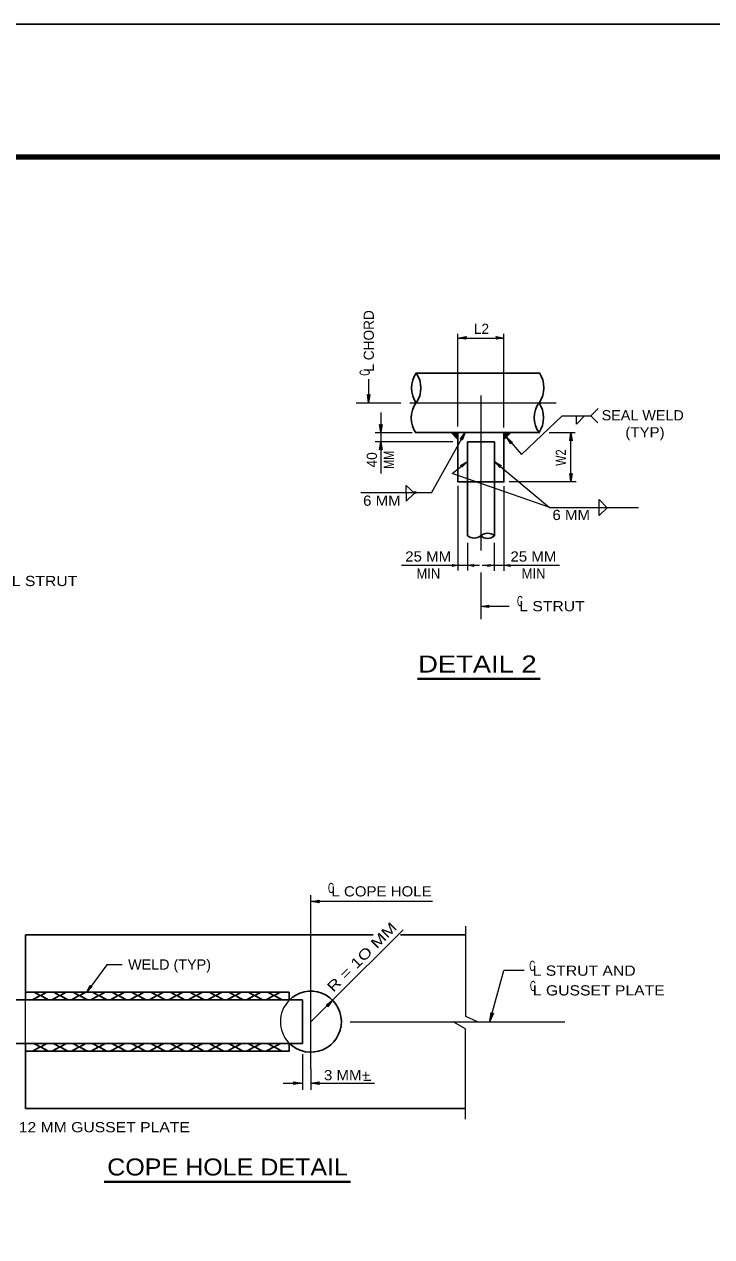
# Model space of a CAD drawing. Extents: x 312601.858 to 312602.699, y 144420.109 to 144420.704.
# Drawn here: x 312602.1064 to 312602.3083, y 144420.3472 to 144420.7035 of the extents above; entities that cross this region are included whole.
import ezdxf
from ezdxf.enums import TextEntityAlignment as Align

# ---------------------------------------------------------------- set-up
doc = ezdxf.new("R2010")
doc.units = 0
doc.header["$LTSCALE"] = 0.0012
doc.header["$PDMODE"] = 32
doc.header["$PDSIZE"] = 0.0006
for name, pattern in [('DOT_DASHED', [7.7, 5, -1.2, 0.3, -1.2]), ('DOTTED', [1.5, 0.3, -1.2]), ('MEDIUM_DASHED', [4.5, 3, -1.5])]:
    doc.linetypes.add(name, pattern=pattern)
for name, color, linetype, lineweight in [('1', 7, 'Continuous', 13), ('2', 7, 'Continuous', 13), ('39', 7, 'Continuous', 13)]:
    doc.layers.add(name, color=color, linetype=linetype, lineweight=lineweight)

msp = doc.modelspace()

# ---------------------------------------------------------------- hatches: boundary and pattern name
at = {"layer": '2'}
for points in [[(312602.2318, 144420.5835), (312602.2338, 144420.5835), (312602.2338, 144420.5815)], [(312602.2493, 144420.5835), (312602.2473, 144420.5835), (312602.2473, 144420.5815)]]:
    msp.add_hatch(color=256, dxfattribs=at).paths.add_polyline_path(points)
at = {"layer": '39'}
for points in [[(312602.236, 144420.6113), (312602.2362, 144420.611), (312602.2338, 144420.6113), (312602.2362, 144420.6117)], [(312602.2452, 144420.6113), (312602.245, 144420.6117), (312602.2474, 144420.6113), (312602.245, 144420.611)], [(312602.2075, 144420.5945), (312602.2079, 144420.5947), (312602.2075, 144420.5923), (312602.2072, 144420.5947)], [(312602.2111, 144420.5857), (312602.2115, 144420.5859), (312602.2111, 144420.5835), (312602.2108, 144420.5859)], [(312602.2348, 144420.5816), (312602.2344, 144420.5816), (312602.2359, 144420.5835), (312602.235, 144420.5813)], [(312602.2669, 144420.5813), (312602.2666, 144420.5811), (312602.2669, 144420.5835), (312602.2673, 144420.5811)], [(312602.2111, 144420.5786), (312602.2108, 144420.5784), (312602.2111, 144420.5808), (312602.2115, 144420.5784)], [(312602.2494, 144420.5806), (312602.2493, 144420.5802), (312602.248, 144420.5822), (312602.2498, 144420.5806)], [(312602.2494, 144420.5806), (312602.2493, 144420.5802), (312602.248, 144420.5822), (312602.2498, 144420.5806)], [(312602.2349, 144420.5737), (312602.2345, 144420.5738), (312602.2366, 144420.575), (312602.2349, 144420.5733)], [(312602.2462, 144420.5736), (312602.2461, 144420.5732), (312602.2445, 144420.575), (312602.2466, 144420.5737)], [(312602.2669, 144420.5713), (312602.2673, 144420.5715), (312602.2669, 144420.5691), (312602.2666, 144420.5715)], [(312602.2427, 144420.5324), (312602.2429, 144420.5321), (312602.2405, 144420.5324), (312602.2429, 144420.5328)], [(312602.2427, 144420.5324), (312602.2429, 144420.5321), (312602.2405, 144420.5324), (312602.2429, 144420.5328)], [(312602.1928, 144420.4457), (312602.193, 144420.4453), (312602.1906, 144420.4457), (312602.193, 144420.4461)], [(312602.126, 144420.4207), (312602.1264, 144420.4207), (312602.1247, 144420.419), (312602.1258, 144420.4211)], [(312602.1955, 144420.4152), (312602.1951, 144420.4153), (312602.197, 144420.4167), (312602.1956, 144420.4148)], [(312602.2438, 144420.4127), (312602.2442, 144420.4129), (312602.2432, 144420.4105), (312602.2435, 144420.4131)], [(312602.1858, 144420.3923), (312602.1855, 144420.3927), (312602.1881, 144420.3923), (312602.1855, 144420.3919)], [(312602.1858, 144420.3923), (312602.1855, 144420.3927), (312602.1881, 144420.3923), (312602.1855, 144420.3919)], [(312602.1928, 144420.3923), (312602.193, 144420.3919), (312602.1906, 144420.3923), (312602.193, 144420.3927)]]:
    msp.add_hatch(color=256, dxfattribs=at).paths.add_polyline_path(points)

# ---------------------------------------------------------------- linework, layer by layer
at = {"layer": '1'}
for p, q in [((312602.2338, 144420.5853), (312602.2338, 144420.6125)), ((312602.2338, 144420.6113), (312602.2473, 144420.6113)), ((312602.2473, 144420.585), (312602.2473, 144420.6125)), ((312602.2075, 144420.5992), (312602.2075, 144420.5923)), ((312602.2039, 144420.5923), (312602.217, 144420.5923)), ((312602.2095, 144420.5835), (312602.2203, 144420.5835)), ((312602.226, 144420.5658), (312602.2359, 144420.5835)), ((312602.2606, 144420.5835), (312602.2682, 144420.5835)), ((312602.2669, 144420.5691), (312602.2669, 144420.5835)), ((312602.2323, 144420.5808), (312602.2095, 144420.5808)), ((312602.2111, 144420.5808), (312602.2111, 144420.5715)), ((312602.2445, 144420.575), (312602.2607, 144420.5615)), ((312602.2488, 144420.5691), (312602.2685, 144420.5691)), ((312602.2261, 144420.5658), (312602.2053, 144420.5658)), ((312602.2186, 144420.5657), (312602.2186, 144420.568)), ((312602.221, 144420.5657), (312602.2186, 144420.568)), ((312602.2186, 144420.5657), (312602.2186, 144420.5634)), ((312602.221, 144420.5657), (312602.2186, 144420.5634)), ((312602.2338, 144420.5679), (312602.2338, 144420.543)), ((312602.2473, 144420.5678), (312602.2473, 144420.5429)), ((312602.2608, 144420.5615), (312602.2868, 144420.5615)), ((312602.2366, 144420.5511), (312602.2366, 144420.543)), ((312602.2444, 144420.5511), (312602.2444, 144420.5429)), ((312602.2172, 144420.5445), (312602.2401, 144420.5445)), ((312602.2243, 144420.5445), (312602.2401, 144420.5445)), ((312602.2409, 144420.5445), (312602.2549, 144420.5445)), ((312602.241, 144420.5445), (312602.2636, 144420.5445)), ((312602.2405, 144420.5424), (312602.2405, 144420.5287)), ((312602.2488, 144420.5324), (312602.2405, 144420.5324)), ((312602.2432, 144420.4105), (312602.2473, 144420.4254)), ((312602.2532, 144420.4254), (312602.2473, 144420.4254)), ((312602.1825, 144420.3923), (312602.1881, 144420.3923)), ((312602.1906, 144420.3923), (312602.2093, 144420.3923)), ((312602.2062, 144420.3932), (312602.2082, 144420.3932))]:
    msp.add_line(p, q, dxfattribs=at)
at = {"layer": '1', "lineweight": 25}
for p, q in [((312602.2214, 144420.601), (312602.2578, 144420.601)), ((312602.2213, 144420.5835), (312602.2578, 144420.5835)), ((312602.2366, 144420.5808), (312602.2445, 144420.5808)), ((312602.2366, 144420.5808), (312602.2366, 144420.5532)), ((312602.2445, 144420.5808), (312602.2445, 144420.5532)), ((312602.1068, 144420.4168), (312602.1068, 144420.4359)), ((312602.1068, 144420.4359), (312602.2089, 144420.4359)), ((312602.2169, 144420.4359), (312602.2361, 144420.4359)), ((312602.1068, 144420.4191), (312602.1842, 144420.4191)), ((312602.1842, 144420.4168), (312602.1842, 144420.4191)), ((312602.0921, 144420.4168), (312602.1881, 144420.4168)), ((312602.1881, 144420.404), (312602.1881, 144420.4168)), ((312602.0921, 144420.404), (312602.1881, 144420.404)), ((312602.1068, 144420.3849), (312602.1068, 144420.404)), ((312602.1068, 144420.3849), (312602.236, 144420.3849))]:
    msp.add_line(p, q, dxfattribs=at)
at = {"layer": '1', "linetype": 'DOT_DASHED'}
for p, q in [((312602.2405, 144420.5944), (312602.2405, 144420.5489)), ((312602.2197, 144420.5923), (312602.2626, 144420.5923))]:
    msp.add_line(p, q, dxfattribs=at)
at = {"layer": '1', "linetype": 'MEDIUM_DASHED', "lineweight": 25}
msp.add_line((312602.2368, 144420.569), (312602.2444, 144420.569), dxfattribs=at)
at = {"layer": '1', "lineweight": 40}
for p, q in [((312602.2219, 144420.5111), (312602.2579, 144420.5111)), ((312602.1299, 144420.3633), (312602.2022, 144420.3633))]:
    msp.add_line(p, q, dxfattribs=at)
at = {"layer": '1', "linetype": 'DOTTED'}
msp.add_line((312602.1068, 144420.404), (312602.1068, 144420.4168), dxfattribs=at)
at = {"layer": '1'}
for points in [[(312602.2111, 144420.5894), (312602.2111, 144420.5835), (312602.2111, 144420.5808)], [(312602.2338, 144420.5829), (312602.2338, 144420.569), (312602.2366, 144420.569)], [(312602.1906, 144420.4104), (312602.197, 144420.4167), (312602.2177, 144420.4374)], [(312602.236, 144420.3818), (312602.236, 144420.4083), (312602.2324, 144420.4104), (312602.2395, 144420.4104), (312602.2361, 144420.4119), (312602.2361, 144420.4385)]]:
    msp.add_lwpolyline(points, dxfattribs=at)
at = {"layer": '1', "lineweight": 25}
for points in [[(312602.2338, 144420.5835), (312602.2338, 144420.569), (312602.2366, 144420.569)], [(312602.2473, 144420.5835), (312602.2473, 144420.569), (312602.2445, 144420.569)], [(312602.1068, 144420.4017), (312602.1842, 144420.4017), (312602.1842, 144420.404)]]:
    msp.add_lwpolyline(points, dxfattribs=at)
at = {"layer": '1'}
for points in [[(312602.2321, 144420.5447), (312602.2341, 144420.5445), (312602.2321, 144420.5442), (312602.2324, 144420.5445)], [(312602.2385, 144420.5442), (312602.2365, 144420.5445), (312602.2385, 144420.5447), (312602.2382, 144420.5445)], [(312602.2426, 144420.5447), (312602.2445, 144420.5445), (312602.2426, 144420.5442), (312602.2428, 144420.5445)], [(312602.2491, 144420.5442), (312602.2472, 144420.5445), (312602.2491, 144420.5447), (312602.2489, 144420.5445)]]:
    msp.add_lwpolyline(points, close=True, dxfattribs=at)
at = {"layer": '1', "lineweight": 25}
msp.add_arc((312602.1906, 144420.4104), 0.0089627, 225.68206, 136.37292, dxfattribs=at)
at = {"layer": '1', "linetype": 'DOTTED'}
msp.add_arc((312602.1906, 144420.4104), 0.0089627, 136.81298, 222.70939, dxfattribs=at)
at = {"layer": '1'}
msp.add_point((312602.2212, 144420.5659), dxfattribs=at)
at = {"layer": '2'}
for p, q in [((312602.275, 144420.5906), (312602.2728, 144420.5884)), ((312602.271, 144420.5884), (312602.2686, 144420.586)), ((312602.2686, 144420.586), (312602.2686, 144420.5883)), ((312602.2749, 144420.5864), (312602.2728, 144420.5884)), ((312602.1906, 144420.4423), (312602.1906, 144420.4476)), ((312602.2263, 144420.4457), (312602.1906, 144420.4457)), ((312602.1881, 144420.4009), (312602.1881, 144420.3904)), ((312602.1906, 144420.3965), (312602.1906, 144420.3904))]:
    msp.add_line(p, q, dxfattribs=at)
at = {"layer": '2', "linetype": 'DOT_DASHED'}
for p, q in [((312602.1906, 144420.3965), (312602.1906, 144420.443)), ((312602.0021, 144420.4104), (312602.2652, 144420.4104))]:
    msp.add_line(p, q, dxfattribs=at)
at = {"layer": '2'}
for points in [[(312602.248, 144420.5822), (312602.2525, 144420.5771), (312602.2644, 144420.5884), (312602.2728, 144420.5884)], [(312602.2608, 144420.5615), (312602.2321, 144420.5715), (312602.2366, 144420.575)], [(312602.1352, 144420.4271), (312602.1307, 144420.4271), (312602.1247, 144420.419)]]:
    msp.add_lwpolyline(points, dxfattribs=at)
for points in [[(312602.2318, 144420.5835), (312602.2338, 144420.5835), (312602.2338, 144420.5815)], [(312602.2493, 144420.5835), (312602.2473, 144420.5835), (312602.2473, 144420.5815)], [(312602.2753, 144420.5591), (312602.2753, 144420.5638), (312602.2776, 144420.5614)]]:
    msp.add_lwpolyline(points, close=True, dxfattribs=at)
at = {"layer": '2', "lineweight": 25}
for centre, radius, start, end in [((312602.228292, 144420.5966), 0.0080929, 147.06517, 212.93482), ((312602.215286, 144420.5966), 0.0076143, 324.69975, 35.30025), ((312602.250908, 144420.5967), 0.0080929, 327.06517, 32.93482), ((312602.228192, 144420.5878), 0.0080929, 147.06517, 212.93482), ((312602.263814, 144420.5879), 0.0076143, 144.69975, 215.30025), ((312602.250808, 144420.5879), 0.0080929, 327.06517, 32.93482), ((312602.238584, 144420.555447), 0.0029531, 228.35069, 310.44664), ((312602.2425, 144420.5553), 0.0029, 226.39718, 313.60282), ((312602.2425, 144420.550757), 0.0031571, 50.69235, 129.30765)]:
    msp.add_arc(centre, radius, start, end, dxfattribs=at)
at = {"layer": '39', "lineweight": 25}
msp.add_line((312601.8578, 144420.7035), (312602.6988, 144420.7035), dxfattribs=at)
at = {"layer": '39', "lineweight": 158}
msp.add_lwpolyline([(312601.9088, 144420.1247), (312601.9088, 144420.6645), (312602.6838, 144420.6645)], dxfattribs=at)
at = {"layer": '39'}
for points in [[(312602.236, 144420.6113), (312602.2362, 144420.611), (312602.2338, 144420.6113), (312602.2362, 144420.6117)], [(312602.2452, 144420.6113), (312602.245, 144420.6117), (312602.2474, 144420.6113), (312602.245, 144420.611)], [(312602.2075, 144420.5945), (312602.2079, 144420.5947), (312602.2075, 144420.5923), (312602.2072, 144420.5947)], [(312602.2111, 144420.5857), (312602.2115, 144420.5859), (312602.2111, 144420.5835), (312602.2108, 144420.5859)], [(312602.2348, 144420.5816), (312602.2344, 144420.5816), (312602.2359, 144420.5835), (312602.235, 144420.5813)], [(312602.2669, 144420.5813), (312602.2666, 144420.5811), (312602.2669, 144420.5835), (312602.2673, 144420.5811)], [(312602.2111, 144420.5786), (312602.2108, 144420.5784), (312602.2111, 144420.5808), (312602.2115, 144420.5784)], [(312602.2494, 144420.5806), (312602.2493, 144420.5802), (312602.248, 144420.5822), (312602.2498, 144420.5806)], [(312602.2494, 144420.5806), (312602.2493, 144420.5802), (312602.248, 144420.5822), (312602.2498, 144420.5806)], [(312602.2349, 144420.5737), (312602.2345, 144420.5738), (312602.2366, 144420.575), (312602.2349, 144420.5733)], [(312602.2462, 144420.5736), (312602.2461, 144420.5732), (312602.2445, 144420.575), (312602.2466, 144420.5737)], [(312602.2669, 144420.5713), (312602.2673, 144420.5715), (312602.2669, 144420.5691), (312602.2666, 144420.5715)], [(312602.2427, 144420.5324), (312602.2429, 144420.5321), (312602.2405, 144420.5324), (312602.2429, 144420.5328)], [(312602.2427, 144420.5324), (312602.2429, 144420.5321), (312602.2405, 144420.5324), (312602.2429, 144420.5328)], [(312602.1928, 144420.4457), (312602.193, 144420.4453), (312602.1906, 144420.4457), (312602.193, 144420.4461)], [(312602.126, 144420.4207), (312602.1264, 144420.4207), (312602.1247, 144420.419), (312602.1258, 144420.4211)], [(312602.1955, 144420.4152), (312602.1951, 144420.4153), (312602.197, 144420.4167), (312602.1956, 144420.4148)], [(312602.2438, 144420.4127), (312602.2442, 144420.4129), (312602.2432, 144420.4105), (312602.2435, 144420.4131)], [(312602.1858, 144420.3923), (312602.1855, 144420.3927), (312602.1881, 144420.3923), (312602.1855, 144420.3919)], [(312602.1858, 144420.3923), (312602.1855, 144420.3927), (312602.1881, 144420.3923), (312602.1855, 144420.3919)], [(312602.1928, 144420.3923), (312602.193, 144420.3919), (312602.1906, 144420.3923), (312602.193, 144420.3927)]]:
    msp.add_lwpolyline(points, close=True, dxfattribs=at)

# ---------------------------------------------------------------- texts
at = {"layer": '1', "width": 2.85}
for p in [(312602.1455, 144420.4169), (312602.1455, 144420.4018)]:
    msp.add_text('xxxxxxxxxxxxx', height=0.003, dxfattribs=at).set_placement(p, align=Align.CENTER)
at = {"layer": '2'}
for s, p in [('L CHORD', (312602.2091, 144420.61045)), ('40', (312602.21, 144420.5755))]:
    msp.add_text(s, height=0.003, rotation=90, dxfattribs=at).set_placement(p, align=Align.CENTER)
msp.add_text('L2', height=0.003, dxfattribs=at).set_placement((312602.2407, 144420.6125), align=Align.CENTER)
for s, rotation, width, p in [('C', 90, 0.6, (312602.2079, 144420.6011)), ('MM', 90, 0.8, (312602.215, 144420.5755)), ('W2', 90, 0.8, (312602.2655, 144420.57615)), ('R = 1O MM', 45, 1.3, (312602.206639, 144420.428339))]:
    msp.add_text(s, height=0.003, rotation=rotation, dxfattribs=dict(at, width=width)).set_placement(p, align=Align.CENTER)
for s, height, width, p in [('SEAL WELD', 0.003, 1.05, (312602.28805, 144420.5871)), (' (TYP)', 0.003, 1.1, (312602.2881, 144420.5821)), ('6 MM', 0.003, 1.1, (312602.21145, 144420.562)), ('6 MM', 0.003, 1.1, (312602.26705, 144420.5578)), ('25 MM', 0.003, 1.1, (312602.22505, 144420.5456)), ('25 MM', 0.003, 1.1, (312602.25595, 144420.5456)), ('MIN', 0.003, 0.95, (312602.2251, 144420.5406)), ('MIN', 0.003, 0.95, (312602.256, 144420.5406)), ('L STRUT', 0.003, 1.15, (312602.1124, 144420.5384)), ('C', 0.003, 0.6, (312602.252, 144420.5325)), ('L STRUT', 0.003, 1.15, (312602.2614, 144420.531)), ('DETAIL 2', 0.005, 1.2, (312602.2395, 144420.513)), ('C', 0.003, 0.6, (312602.1965, 144420.4482)), ('L COPE HOLE', 0.003, 1.1, (312602.21135, 144420.4472)), ('WELD (TYP)', 0.003, 1.05, (312602.1491, 144420.4257)), ('C', 0.003, 0.6, (312602.2556, 144420.4253)), ('L STRUT AND', 0.003, 1.15, (312602.27085, 144420.4239)), ('C', 0.003, 0.6, (312602.2558, 144420.4194)), ('L GUSSET PLATE', 0.003, 1.15, (312602.27515, 144420.4181)), ('3 MM+', 0.003, 1.1, (312602.20125, 144420.3932)), ('12 MM GUSSET PLATE', 0.003, 1.15, (312602.12995, 144420.3779)), ('COPE HOLE DETAIL', 0.005, 1.1, (312602.16615, 144420.3652))]:
    msp.add_text(s, height=height, dxfattribs=dict(at, width=width)).set_placement(p, align=Align.CENTER)

doc.saveas('drawing.dxf')
